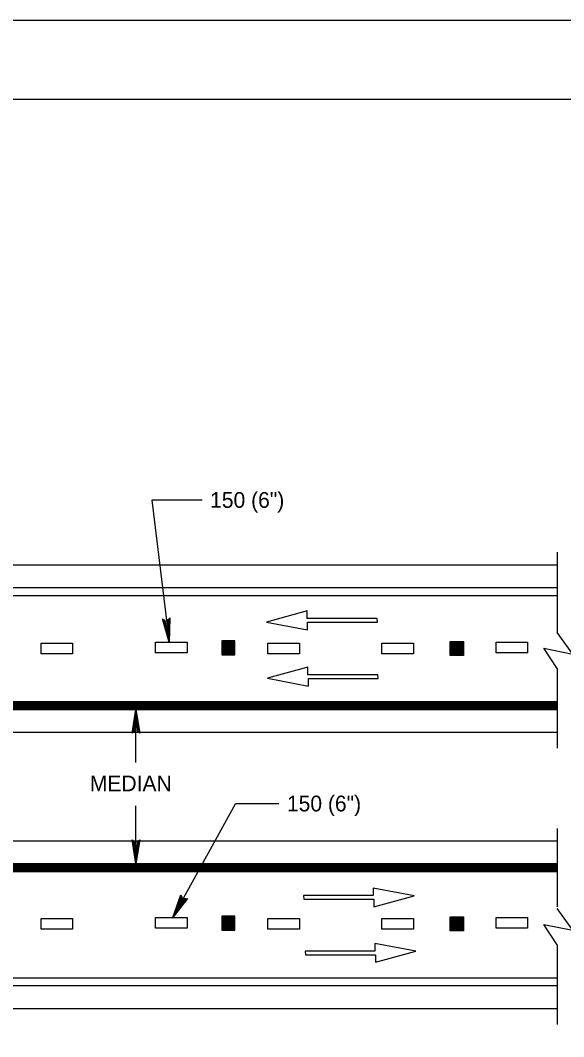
# Model space of a CAD drawing. Extents: x 639362 to 641108, y 298458 to 299646.
# Drawn here: x 639975.6 to 640079.2, y 299452 to 299645.6 of the extents above; entities that cross this region are included whole.
import ezdxf

# ---------------------------------------------------------------- set-up
doc = ezdxf.new("R2010")
doc.units = 0
for name, color, linetype in [('1', 7, 'Continuous'), ('2', 7, 'Continuous'), ('PLT-BNDY', 7, 'Continuous')]:
    doc.layers.add(name, color=color, linetype=linetype)

msp = doc.modelspace()

# ---------------------------------------------------------------- linework, layer by layer
at = {"layer": '1'}
msp.add_line((639402.31, 299630.63), (640188.31, 299630.63), dxfattribs=at)
at = {"layer": '2'}
for p, q in [((640000.66, 299554.2), (640003.95, 299527.19)), ((640010.28, 299554.2), (640000.66, 299554.2)), ((640077.95, 299544.29), (640077.95, 299529.01)), ((639843.44, 299541.93), (640077.95, 299541.93)), ((639843.44, 299537.58), (640077.95, 299537.58)), ((639843.44, 299536.08), (640077.95, 299536.08)), ((640030.27, 299533.11), (640022.55, 299530.99)), ((640030.27, 299531.67), (640030.27, 299533.11)), ((640022.55, 299530.99), (640030.35, 299529.52)), ((640043.6, 299531.67), (640030.27, 299531.67)), ((640030.35, 299529.52), (640030.35, 299530.96)), ((640030.35, 299530.96), (640043.68, 299530.96)), ((640043.68, 299530.99), (640043.6, 299531.67)), ((640043.68, 299530.96), (640043.68, 299530.99)), ((640080.9, 299524.88), (640077.95, 299529.01)), ((639979.56, 299524.93), (639979.56, 299527)), ((639979.56, 299527), (639985.57, 299527)), ((639985.57, 299527), (639985.57, 299524.93)), ((640001.36, 299525.12), (640001.36, 299527.19)), ((640001.36, 299527.19), (640007.38, 299527.19)), ((640007.38, 299527.19), (640007.38, 299525.12)), ((640016.5, 299527.42), (640014.01, 299527.42)), ((640014.01, 299527.42), (640014.01, 299524.77)), ((640016.32, 299527.29), (640014.19, 299527.29)), ((640014.19, 299527.29), (640014.19, 299524.89)), ((640016.14, 299527.11), (640014.36, 299527.11)), ((640014.36, 299527.11), (640014.36, 299525.07)), ((640015.96, 299526.93), (640014.54, 299526.93)), ((640014.54, 299526.93), (640014.54, 299525.25)), ((640015.79, 299526.76), (640014.72, 299526.76)), ((640014.72, 299526.76), (640014.72, 299525.43)), ((640014.9, 299526.58), (640014.9, 299525.6)), ((640015.61, 299526.58), (640014.9, 299526.58)), ((640015.43, 299526.4), (640015.07, 299526.4)), ((640015.07, 299526.4), (640015.07, 299525.78)), ((640015.43, 299525.78), (640015.43, 299526.4)), ((640015.61, 299525.6), (640015.61, 299526.58)), ((640015.79, 299525.43), (640015.79, 299526.76)), ((640015.96, 299525.25), (640015.96, 299526.93)), ((640016.14, 299525.07), (640016.14, 299527.11)), ((640016.32, 299524.89), (640016.32, 299527.29)), ((640016.5, 299524.77), (640016.5, 299527.42)), ((640022.81, 299524.93), (640022.81, 299527)), ((640022.81, 299527), (640028.83, 299527)), ((640028.83, 299527), (640028.83, 299524.93)), ((640044.51, 299524.93), (640044.51, 299527)), ((640044.51, 299527), (640050.53, 299527)), ((640050.53, 299527), (640050.53, 299524.93)), ((640057.56, 299527.3), (640060.06, 299527.3)), ((640057.56, 299524.65), (640057.56, 299527.3)), ((640057.75, 299527.17), (640059.88, 299527.17)), ((640057.75, 299524.77), (640057.75, 299527.17)), ((640057.93, 299526.99), (640059.7, 299526.99)), ((640057.93, 299524.95), (640057.93, 299526.99)), ((640058.1, 299526.81), (640059.52, 299526.81)), ((640058.1, 299525.13), (640058.1, 299526.81)), ((640058.28, 299526.64), (640059.35, 299526.64)), ((640058.28, 299525.31), (640058.28, 299526.64)), ((640058.46, 299525.48), (640058.46, 299526.46)), ((640058.46, 299526.46), (640059.17, 299526.46)), ((640059.17, 299526.46), (640059.17, 299525.48)), ((640059.35, 299526.64), (640059.35, 299525.31)), ((640059.52, 299526.81), (640059.52, 299525.13)), ((640059.7, 299526.99), (640059.7, 299524.95)), ((640059.88, 299527.17), (640059.88, 299524.77)), ((640060.06, 299527.3), (640060.06, 299524.65)), ((640066.28, 299525.12), (640066.28, 299527.19)), ((640066.28, 299527.19), (640072.29, 299527.19)), ((640072.29, 299527.19), (640072.29, 299525.12)), ((639985.57, 299524.93), (639979.56, 299524.93)), ((640007.38, 299525.12), (640001.36, 299525.12)), ((640014.01, 299524.77), (640016.5, 299524.77)), ((640014.19, 299524.89), (640016.32, 299524.89)), ((640014.36, 299525.07), (640016.14, 299525.07)), ((640014.54, 299525.25), (640015.96, 299525.25)), ((640014.72, 299525.43), (640015.79, 299525.43)), ((640014.9, 299525.6), (640015.61, 299525.6)), ((640015.07, 299525.78), (640015.43, 299525.78)), ((640015.25, 299526.23), (640015.25, 299525.96)), ((640028.83, 299524.93), (640022.81, 299524.93)), ((640050.53, 299524.93), (640044.51, 299524.93)), ((640060.06, 299524.65), (640057.56, 299524.65)), ((640059.88, 299524.77), (640057.75, 299524.77)), ((640059.7, 299524.95), (640057.93, 299524.95)), ((640059.52, 299525.13), (640058.1, 299525.13)), ((640059.35, 299525.31), (640058.28, 299525.31)), ((640059.17, 299525.48), (640058.46, 299525.48)), ((640058.64, 299526.28), (640058.99, 299526.28)), ((640058.64, 299525.66), (640058.64, 299526.28)), ((640058.99, 299525.66), (640058.64, 299525.66)), ((640058.81, 299526.11), (640058.81, 299525.84)), ((640058.99, 299526.28), (640058.99, 299525.66)), ((640072.29, 299525.12), (640066.28, 299525.12)), ((640077.95, 299522.15), (640075.37, 299526.02)), ((640075.37, 299526.02), (640080.9, 299524.88)), ((640030.43, 299522.4), (640022.7, 299520.28)), ((640030.43, 299520.96), (640030.43, 299522.4)), ((640043.75, 299520.96), (640030.43, 299520.96)), ((640043.83, 299520.28), (640043.75, 299520.96)), ((640077.95, 299522.15), (640077.95, 299506.96)), ((640022.7, 299520.28), (640030.51, 299518.81)), ((640030.51, 299518.81), (640030.51, 299520.25)), ((640030.51, 299520.25), (640043.83, 299520.25)), ((640043.83, 299520.25), (640043.83, 299520.28)), ((639843.44, 299515.85), (640077.95, 299515.85)), ((639843.44, 299515.7), (640077.95, 299515.7)), ((639843.44, 299515.55), (640077.95, 299515.55)), ((639843.44, 299515.4), (640077.95, 299515.4)), ((639843.44, 299515.25), (640077.95, 299515.25)), ((639843.44, 299515.1), (640077.95, 299515.1)), ((639843.44, 299514.95), (640077.95, 299514.95)), ((639843.44, 299514.8), (640077.95, 299514.8)), ((639843.44, 299514.65), (640077.95, 299514.65)), ((639843.44, 299514.5), (640077.95, 299514.5)), ((639843.44, 299514.35), (640077.95, 299514.35)), ((639997.64, 299504.24), (639997.64, 299514.35)), ((639843.44, 299510), (640077.95, 299510)), ((639997.64, 299484.98), (639997.64, 299496.01)), ((640004.66, 299474.74), (640016.63, 299496.34)), ((640024.86, 299496.34), (640016.63, 299496.34)), ((640077.95, 299491.69), (640077.95, 299476.75)), ((639843.44, 299489.33), (640077.95, 299489.33)), ((639843.44, 299484.98), (640077.95, 299484.98)), ((639843.44, 299484.83), (640077.95, 299484.83)), ((639843.44, 299484.68), (640077.95, 299484.68)), ((639843.44, 299484.53), (640077.95, 299484.53)), ((639843.44, 299484.38), (640077.95, 299484.38)), ((639843.44, 299484.23), (640077.95, 299484.23)), ((639843.44, 299484.08), (640077.95, 299484.08)), ((639843.44, 299483.93), (640077.95, 299483.93)), ((639843.44, 299483.78), (640077.95, 299483.78)), ((639843.44, 299483.63), (640077.95, 299483.63)), ((639843.44, 299483.48), (640077.95, 299483.48)), ((640050.69, 299478.86), (640042.88, 299480.33)), ((640042.88, 299480.33), (640042.88, 299478.89)), ((640029.56, 299478.89), (640029.56, 299478.86)), ((640042.88, 299478.89), (640029.56, 299478.89)), ((640029.56, 299478.86), (640029.64, 299478.19)), ((640029.64, 299478.19), (640042.96, 299478.19)), ((640042.96, 299476.74), (640050.69, 299478.86)), ((640042.96, 299478.19), (640042.96, 299476.74)), ((640080.9, 299472.28), (640077.95, 299476.41)), ((639979.56, 299472.49), (639979.56, 299474.55)), ((639979.56, 299474.55), (639985.57, 299474.55)), ((639985.57, 299474.55), (639985.57, 299472.49)), ((640001.36, 299472.68), (640001.36, 299474.74)), ((640001.36, 299474.74), (640007.38, 299474.74)), ((640007.38, 299474.74), (640007.38, 299472.68)), ((640016.5, 299474.98), (640014.01, 299474.98)), ((640014.01, 299474.98), (640014.01, 299472.32)), ((640016.32, 299474.84), (640014.19, 299474.84)), ((640014.19, 299474.84), (640014.19, 299472.45)), ((640016.14, 299474.67), (640014.36, 299474.67)), ((640014.36, 299474.67), (640014.36, 299472.63)), ((640015.96, 299474.49), (640014.54, 299474.49)), ((640014.54, 299474.49), (640014.54, 299472.8)), ((640015.79, 299474.31), (640014.72, 299474.31)), ((640014.72, 299474.31), (640014.72, 299472.98)), ((640014.9, 299474.13), (640014.9, 299473.16)), ((640015.61, 299474.13), (640014.9, 299474.13)), ((640015.61, 299473.16), (640015.61, 299474.13)), ((640015.79, 299472.98), (640015.79, 299474.31)), ((640015.96, 299472.8), (640015.96, 299474.49)), ((640016.14, 299472.63), (640016.14, 299474.67)), ((640016.32, 299472.45), (640016.32, 299474.84)), ((640016.5, 299472.32), (640016.5, 299474.98)), ((640022.81, 299472.49), (640022.81, 299474.55)), ((640022.81, 299474.55), (640028.83, 299474.55)), ((640028.83, 299474.55), (640028.83, 299472.49)), ((640044.51, 299472.49), (640044.51, 299474.55)), ((640044.51, 299474.55), (640050.53, 299474.55)), ((640050.53, 299474.55), (640050.53, 299472.49)), ((640057.56, 299474.86), (640060.06, 299474.86)), ((640057.56, 299472.2), (640057.56, 299474.86)), ((640057.75, 299474.72), (640059.88, 299474.72)), ((640057.75, 299472.33), (640057.75, 299474.72)), ((640057.93, 299474.55), (640059.7, 299474.55)), ((640057.93, 299472.51), (640057.93, 299474.55)), ((640058.1, 299474.37), (640059.52, 299474.37)), ((640058.1, 299472.68), (640058.1, 299474.37)), ((640058.28, 299474.19), (640059.35, 299474.19)), ((640058.28, 299472.86), (640058.28, 299474.19)), ((640059.35, 299474.19), (640059.35, 299472.86)), ((640059.52, 299474.37), (640059.52, 299472.68)), ((640059.7, 299474.55), (640059.7, 299472.51)), ((640059.88, 299474.72), (640059.88, 299472.33)), ((640060.06, 299474.86), (640060.06, 299472.2)), ((640066.28, 299472.68), (640066.28, 299474.74)), ((640066.28, 299474.74), (640072.29, 299474.74)), ((640072.29, 299474.74), (640072.29, 299472.68)), ((639985.57, 299472.49), (639979.56, 299472.49)), ((640007.38, 299472.68), (640001.36, 299472.68)), ((640014.01, 299472.32), (640016.5, 299472.32)), ((640014.19, 299472.45), (640016.32, 299472.45)), ((640014.36, 299472.63), (640016.14, 299472.63)), ((640014.54, 299472.8), (640015.96, 299472.8)), ((640014.72, 299472.98), (640015.79, 299472.98)), ((640014.9, 299473.16), (640015.61, 299473.16)), ((640015.43, 299473.96), (640015.07, 299473.96)), ((640015.07, 299473.96), (640015.07, 299473.34)), ((640015.07, 299473.34), (640015.43, 299473.34)), ((640015.25, 299473.78), (640015.25, 299473.51)), ((640015.43, 299473.34), (640015.43, 299473.96)), ((640028.83, 299472.49), (640022.81, 299472.49)), ((640050.53, 299472.49), (640044.51, 299472.49)), ((640060.06, 299472.2), (640057.56, 299472.2)), ((640059.88, 299472.33), (640057.75, 299472.33)), ((640059.7, 299472.51), (640057.93, 299472.51)), ((640059.52, 299472.68), (640058.1, 299472.68)), ((640059.35, 299472.86), (640058.28, 299472.86)), ((640058.46, 299473.04), (640058.46, 299474.01)), ((640058.46, 299474.01), (640059.17, 299474.01)), ((640059.17, 299473.04), (640058.46, 299473.04)), ((640058.64, 299473.84), (640058.99, 299473.84)), ((640058.64, 299473.22), (640058.64, 299473.84)), ((640058.99, 299473.22), (640058.64, 299473.22)), ((640058.81, 299473.66), (640058.81, 299473.39)), ((640058.99, 299473.84), (640058.99, 299473.22)), ((640059.17, 299474.01), (640059.17, 299473.04)), ((640072.29, 299472.68), (640066.28, 299472.68)), ((640077.95, 299469.54), (640075.37, 299473.41)), ((640075.37, 299473.41), (640080.9, 299472.28)), ((640029.87, 299468.33), (640029.87, 299468.29)), ((640043.19, 299468.33), (640029.87, 299468.33)), ((640029.87, 299468.29), (640029.95, 299467.62)), ((640051, 299468.29), (640043.19, 299469.77)), ((640043.19, 299469.77), (640043.19, 299468.33)), ((640043.27, 299466.18), (640051, 299468.29)), ((640077.95, 299469.54), (640077.95, 299454.36)), ((640029.95, 299467.62), (640043.27, 299467.62)), ((640043.27, 299467.62), (640043.27, 299466.18)), ((639843.44, 299463.25), (640077.95, 299463.25)), ((639843.44, 299461.75), (640077.95, 299461.75)), ((639843.44, 299457.4), (640077.95, 299457.4))]:
    msp.add_line(p, q, dxfattribs=at)
for points in [[(640003.96, 299531.54), (640003.67, 299531.34), (640003.95, 299527.19), (640003.96, 299531.54), (640004.13, 299531.78), (640003.95, 299527.19), (640003.24, 299531.29), (640002.92, 299531.4), (640003.95, 299527.19), (640002.69, 299531.61), (640002.92, 299531.4)], [(639997.1, 299510.03), (639997.41, 299510.19), (639997.64, 299514.35), (639997.1, 299510.03), (639996.91, 299509.81), (639997.64, 299514.35), (639997.85, 299510.2), (639998.16, 299510.04), (639997.64, 299514.35), (639998.36, 299509.81), (639998.16, 299510.04)], [(639998.18, 299489.3), (639997.87, 299489.14), (639997.64, 299484.98), (639998.18, 299489.3), (639998.38, 299489.52), (639997.64, 299484.98), (639997.44, 299489.13), (639997.13, 299489.28), (639997.64, 299484.98), (639996.92, 299489.52), (639997.13, 299489.28)], [(640007.23, 299478.26), (640006.88, 299478.27), (640004.66, 299474.74), (640007.23, 299478.26), (640007.5, 299478.36), (640004.66, 299474.74), (640006.5, 299478.47), (640006.3, 299478.76), (640004.66, 299474.74), (640006.23, 299479.06), (640006.3, 299478.76)]]:
    msp.add_lwpolyline(points, dxfattribs=at)
at = {"layer": 'PLT-BNDY'}
msp.add_lwpolyline([(639362.31, 299645.63), (640203.31, 299645.63), (640203.31, 299051.63), (639362.31, 299051.63)], close=True, dxfattribs=at)

# ---------------------------------------------------------------- texts
at = {"layer": '2'}
for s, p in [('150 (6")', (640011.78, 299552.76)), ('MEDIAN', (639988.86, 299498.76)), ('150 (6")', (640026.42, 299494.93))]:
    msp.add_text(s, height=3, dxfattribs=at).set_placement(p)

doc.saveas('drawing.dxf')
